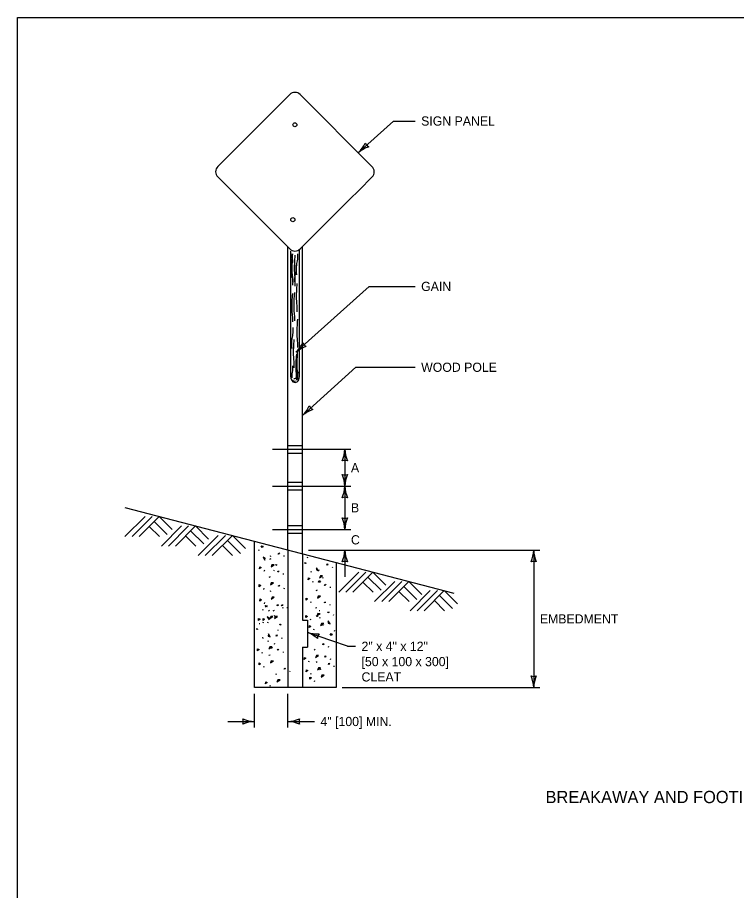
# Model space of a CAD drawing. Extents: x 49991.4 to 50021, y 49987.6 to 50011.4.
# Drawn here: x 49999.38 to 50004.08, y 49993.3 to 49999 of the extents above; entities that cross this region are included whole.
import ezdxf

# ---------------------------------------------------------------- set-up
doc = ezdxf.new("R2010")
doc.units = 0
for name, color, linetype in [('Level 1', 7, 'Continuous'), ('Level 2', 7, 'Continuous'), ('Level 3', 7, 'Continuous'), ('Level 4', 7, 'Continuous'), ('Level 5', 7, 'Continuous')]:
    doc.layers.add(name, color=color, linetype=linetype)

msp = doc.modelspace()

# ---------------------------------------------------------------- linework, layer by layer
at = {"layer": 'Level 1'}
for p, q in [((50001.1615, 49998.4961), (50000.691, 49998.0256)), ((50001.698, 49998.0267), (50001.2287, 49998.4961)), ((50000.691, 49997.9584), (50001.1615, 49997.488)), ((50001.6133, 49997.8726), (50001.6991, 49997.9584)), ((50001.551, 49997.8104), (50001.6133, 49997.8726)), ((50001.2287, 49997.488), (50001.551, 49997.8104)), ((50001.1483, 49995.5227), (50001.1483, 49997.5012)), ((50001.2435, 49995.4979), (50001.2435, 49997.5026)), ((50001.1681, 49996.6528), (50001.1681, 49997.4731)), ((50001.2241, 49996.6528), (50001.2241, 49997.4797)), ((50000.0838, 49995.7996), (50002.2326, 49995.2407)), ((50000.0855, 49995.61), (50000.2167, 49995.7411)), ((50000.1318, 49995.61), (50000.2631, 49995.7411)), ((50000.1773, 49995.61), (50000.3087, 49995.7411)), ((50000.3087, 49995.7411), (50000.3942, 49995.6559)), ((50000.2439, 49995.6761), (50000.3103, 49995.61)), ((50000.2763, 49995.7087), (50000.3616, 49995.6236)), ((50000.3231, 49995.5481), (50000.4542, 49995.6794)), ((50000.3692, 49995.5481), (50000.5004, 49995.6794)), ((50000.4149, 49995.5481), (50000.546, 49995.6794)), ((50000.546, 49995.6794), (50000.6315, 49995.594)), ((50000.4812, 49995.6146), (50000.5478, 49995.5481)), ((50000.5136, 49995.6471), (50000.5991, 49995.5619)), ((50000.5636, 49995.4855), (50000.6947, 49995.6168)), ((50000.6097, 49995.4855), (50000.7409, 49995.6168)), ((50000.6554, 49995.4855), (50000.7865, 49995.6168)), ((50000.7865, 49995.6168), (50000.872, 49995.5314)), ((50000.7217, 49995.552), (50000.7883, 49995.4855)), ((50000.7541, 49995.5845), (50000.8396, 49995.4993)), ((50000.9305, 49994.6238), (50000.9305, 49995.5794)), ((50000.9734, 49995.5491), (50000.987, 49995.5483)), ((50000.9815, 49995.5388), (50000.9734, 49995.5491)), ((50000.987, 49995.5483), (50000.9815, 49995.5388)), ((50000.9631, 49995.5182), (50000.9562, 49995.5208)), ((50001.0858, 49995.4962), (50001.0891, 49995.5039)), ((50001.0931, 49995.498), (50001.0858, 49995.4962)), ((50001.0891, 49995.5039), (50001.0931, 49995.498)), ((50001.1236, 49995.4804), (50001.1243, 49995.4862)), ((50000.9995, 49995.4697), (50000.9866, 49995.4748)), ((50000.9866, 49995.4748), (50000.9991, 49995.455)), ((50000.9991, 49995.455), (50000.9995, 49995.4697)), ((50001.0365, 49995.4638), (50001.0288, 49995.4613)), ((50001.0373, 49995.4771), (50001.0348, 49995.4848)), ((50001.2579, 49995.4372), (50001.2638, 49995.4412)), ((50001.2656, 49995.4339), (50001.2579, 49995.4372)), ((50001.2638, 49995.4412), (50001.2656, 49995.4339)), ((50001.2814, 49995.4717), (50001.2756, 49995.4724)), ((50001.4031, 49995.4235), (50001.4064, 49995.4312)), ((50001.4064, 49995.4312), (50001.4104, 49995.4253)), ((50001.4634, 49995.4409), (50001.4634, 49994.6238)), ((50000.9645, 49995.3999), (50000.9653, 49995.4135)), ((50000.9748, 49995.408), (50000.9645, 49995.3999)), ((50000.9653, 49995.4135), (50000.9748, 49995.408)), ((50000.9954, 49995.3896), (50000.9928, 49995.3827)), ((50001.0439, 49995.426), (50001.0388, 49995.4131)), ((50001.0388, 49995.4131), (50001.0586, 49995.4256)), ((50001.0586, 49995.4256), (50001.0439, 49995.426)), ((50001.0539, 49995.39), (50001.0597, 49995.3893)), ((50001.0697, 49995.4278), (50001.0774, 49995.4245)), ((50001.0715, 49995.4205), (50001.0697, 49995.4278)), ((50001.0774, 49995.4245), (50001.0715, 49995.4205)), ((50001.0825, 49995.3787), (50001.0858, 49995.3864)), ((50001.0898, 49995.3805), (50001.0825, 49995.3787)), ((50001.0858, 49995.3864), (50001.0898, 49995.3805)), ((50001.298, 49995.3846), (50001.3005, 49995.3769)), ((50001.3362, 49995.4067), (50001.3358, 49995.392)), ((50001.3358, 49995.392), (50001.3487, 49995.3869)), ((50001.3487, 49995.3869), (50001.3362, 49995.4067)), ((50001.3538, 49995.3911), (50001.3461, 49995.3886)), ((50001.4104, 49995.4253), (50001.4031, 49995.4235)), ((50001.4409, 49995.4077), (50001.4416, 49995.4135)), ((50001.4807, 49995.247), (50001.6119, 49995.3782)), ((50001.5269, 49995.247), (50001.6583, 49995.3782)), ((50001.5728, 49995.247), (50001.7039, 49995.3782)), ((50001.7039, 49995.3782), (50001.7894, 49995.2932)), ((50001.0332, 49995.3463), (50001.0255, 49995.3438)), ((50001.1203, 49995.3629), (50001.121, 49995.3687)), ((50001.2818, 49995.3272), (50001.2826, 49995.3408)), ((50001.2921, 49995.3353), (50001.2818, 49995.3272)), ((50001.2826, 49995.3408), (50001.2921, 49995.3353)), ((50001.3127, 49995.3169), (50001.3101, 49995.31)), ((50001.3483, 49995.3134), (50001.3538, 49995.3229)), ((50001.3538, 49995.3229), (50001.3619, 49995.3126)), ((50001.3612, 49995.3533), (50001.3561, 49995.3404)), ((50001.3561, 49995.3404), (50001.3759, 49995.3529)), ((50001.3759, 49995.3529), (50001.3612, 49995.3533)), ((50001.3722, 49995.3435), (50001.3791, 49995.3409)), ((50001.6715, 49995.3458), (50001.7568, 49995.2609)), ((50001.7152, 49995.1859), (50001.8463, 49995.3173)), ((50001.7616, 49995.1859), (50001.8927, 49995.3173)), ((50001.807, 49995.1859), (50001.9381, 49995.3173)), ((50001.9381, 49995.3173), (50002.0239, 49995.2318)), ((50000.9612, 49995.2824), (50000.962, 49995.296)), ((50000.9715, 49995.2905), (50000.9612, 49995.2824)), ((50000.962, 49995.296), (50000.9715, 49995.2905)), ((50000.9921, 49995.2721), (50000.9895, 49995.2652)), ((50001.0406, 49995.3085), (50001.0355, 49995.2956)), ((50001.0355, 49995.2956), (50001.0553, 49995.3081)), ((50001.0553, 49995.3081), (50001.0406, 49995.3085)), ((50001.0875, 49995.2853), (50001.0908, 49995.293)), ((50001.0948, 49995.2871), (50001.0875, 49995.2853)), ((50001.0908, 49995.293), (50001.0948, 49995.2871)), ((50001.1253, 49995.2695), (50001.126, 49995.2753)), ((50001.3396, 49995.259), (50001.3319, 49995.2565)), ((50001.3619, 49995.3126), (50001.3483, 49995.3134)), ((50001.3889, 49995.2914), (50001.3922, 49995.2991)), ((50001.3962, 49995.2932), (50001.3889, 49995.2914)), ((50001.3922, 49995.2991), (50001.3962, 49995.2932)), ((50001.4267, 49995.2756), (50001.4274, 49995.2814)), ((50001.6391, 49995.3131), (50001.7052, 49995.247)), ((50001.9057, 49995.2849), (50001.9912, 49995.1995)), ((50000.9662, 49995.189), (50000.967, 49995.2026)), ((50000.967, 49995.2026), (50000.9765, 49995.1971)), ((50001.0382, 49995.2529), (50001.0305, 49995.2504)), ((50001.0456, 49995.2151), (50001.0405, 49995.2022)), ((50001.0405, 49995.2022), (50001.0603, 49995.2147)), ((50001.0603, 49995.2147), (50001.0456, 49995.2151)), ((50001.2676, 49995.1951), (50001.2684, 49995.2087)), ((50001.2779, 49995.2032), (50001.2676, 49995.1951)), ((50001.2684, 49995.2087), (50001.2779, 49995.2032)), ((50001.347, 49995.2212), (50001.3419, 49995.2083)), ((50001.3419, 49995.2083), (50001.3617, 49995.2208)), ((50001.3617, 49995.2208), (50001.347, 49995.2212)), ((50001.8733, 49995.2522), (50001.9398, 49995.1859)), ((50001.947, 49995.1258), (50002.0782, 49995.2569)), ((50001.9932, 49995.1258), (50002.1246, 49995.2569)), ((50002.0388, 49995.1258), (50002.1702, 49995.2569)), ((50002.1378, 49995.2245), (50002.2231, 49995.1394)), ((50002.1702, 49995.2569), (50002.2557, 49995.1717)), ((50000.9765, 49995.1971), (50000.9662, 49995.189)), ((50000.9971, 49995.1787), (50000.9945, 49995.1718)), ((50001.0002, 49995.1596), (50001.0138, 49995.1588)), ((50001.0083, 49995.1493), (50001.0002, 49995.1596)), ((50001.0138, 49995.1588), (50001.0083, 49995.1493)), ((50001.0785, 49995.1587), (50001.0818, 49995.1664)), ((50001.0858, 49995.1605), (50001.0785, 49995.1587)), ((50001.0818, 49995.1664), (50001.0858, 49995.1605)), ((50001.1081, 49995.1587), (50001.1114, 49995.1664)), ((50001.1154, 49995.1605), (50001.1081, 49995.1587)), ((50001.1114, 49995.1664), (50001.1154, 49995.1605)), ((50001.1163, 49995.1429), (50001.117, 49995.1487)), ((50001.1459, 49995.1429), (50001.1466, 49995.1487)), ((50001.2985, 49995.1848), (50001.2959, 49995.1779)), ((50001.3378, 49995.1448), (50001.3301, 49995.1423)), ((50001.3871, 49995.1772), (50001.3904, 49995.1849)), ((50001.3944, 49995.179), (50001.3871, 49995.1772)), ((50001.3904, 49995.1849), (50001.3944, 49995.179)), ((50001.4249, 49995.1614), (50001.4256, 49995.1672)), ((50002.1054, 49995.1919), (50002.1715, 49995.1258)), ((50000.9899, 49995.1287), (50000.983, 49995.1313)), ((50001.0292, 49995.1263), (50001.0215, 49995.1238)), ((50001.0366, 49995.0885), (50001.0315, 49995.0756)), ((50001.0315, 49995.0756), (50001.0513, 49995.0881)), ((50001.0513, 49995.0881), (50001.0366, 49995.0885)), ((50001.0588, 49995.1263), (50001.0511, 49995.1238)), ((50001.0662, 49995.0885), (50001.0611, 49995.0756)), ((50001.0611, 49995.0756), (50001.0809, 49995.0881)), ((50001.0641, 49995.0876), (50001.0616, 49995.0953)), ((50001.0809, 49995.0881), (50001.0662, 49995.0885)), ((50001.2658, 49995.0809), (50001.2666, 49995.0945)), ((50001.2761, 49995.089), (50001.2658, 49995.0809)), ((50001.2666, 49995.0945), (50001.2761, 49995.089)), ((50001.3345, 49995.0904), (50001.3404, 49995.0944)), ((50001.3422, 49995.0871), (50001.3345, 49995.0904)), ((50001.3452, 49995.107), (50001.3401, 49995.0941)), ((50001.3401, 49995.0941), (50001.3599, 49995.1066)), ((50001.3404, 49995.0944), (50001.3422, 49995.0871)), ((50001.3599, 49995.1066), (50001.3452, 49995.107)), ((50001.358, 49995.1249), (50001.3522, 49995.1256)), ((50001.4097, 49995.1121), (50001.413, 49995.1198)), ((50001.417, 49995.1139), (50001.4097, 49995.1121)), ((50001.413, 49995.1198), (50001.417, 49995.1139)), ((50001.4475, 49995.0963), (50001.4482, 49995.1021)), ((50000.9572, 49995.0624), (50000.958, 49995.076)), ((50000.9675, 49995.0705), (50000.9572, 49995.0624)), ((50000.958, 49995.076), (50000.9675, 49995.0705)), ((50000.9666, 49995.0404), (50000.9608, 49995.0411)), ((50000.9881, 49995.0521), (50000.9855, 49995.0452)), ((50000.9868, 49995.0624), (50000.9876, 49995.076)), ((50000.9971, 49995.0705), (50000.9868, 49995.0624)), ((50000.9876, 49995.076), (50000.9971, 49995.0705)), ((50001.0263, 49995.0802), (50001.0134, 49995.0853)), ((50001.0134, 49995.0853), (50001.0259, 49995.0655)), ((50001.0177, 49995.0521), (50001.0151, 49995.0452)), ((50001.0259, 49995.0655), (50001.0263, 49995.0802)), ((50001.0965, 49995.0383), (50001.1042, 49995.035)), ((50001.0983, 49995.031), (50001.0965, 49995.0383)), ((50001.1042, 49995.035), (50001.0983, 49995.031)), ((50001.2884, 49995.0158), (50001.2892, 49995.0294)), ((50001.2892, 49995.0294), (50001.2987, 49995.0239)), ((50001.2967, 49995.0706), (50001.2941, 49995.0637)), ((50001.3604, 49995.0797), (50001.3527, 49995.0772)), ((50001.3678, 49995.0419), (50001.3627, 49995.029)), ((50001.3627, 49995.029), (50001.3825, 49995.0415)), ((50001.3825, 49995.0415), (50001.3678, 49995.0419)), ((50001.3746, 49995.0378), (50001.3771, 49995.0301)), ((50001.4128, 49995.0599), (50001.4124, 49995.0452)), ((50001.4124, 49995.0452), (50001.4253, 49995.0401)), ((50001.4253, 49995.0401), (50001.4128, 49995.0599)), ((50000.9431, 49995.0059), (50000.949, 49995.0099)), ((50000.9508, 49995.0026), (50000.9431, 49995.0059)), ((50000.949, 49995.0099), (50000.9508, 49995.0026)), ((50001.0214, 49994.9754), (50001.021, 49994.9607)), ((50001.0339, 49994.9556), (50001.0214, 49994.9754)), ((50001.0807, 49995.0005), (50001.0865, 49994.9998)), ((50001.2987, 49995.0239), (50001.2884, 49995.0158)), ((50001.3193, 49995.0055), (50001.3167, 49994.9986)), ((50001.4249, 49994.9666), (50001.4304, 49994.9761)), ((50001.4304, 49994.9761), (50001.4385, 49994.9658)), ((50001.4488, 49994.9967), (50001.4557, 49994.9941)), ((50000.9832, 49994.9533), (50000.9857, 49994.9456)), ((50001.0227, 49994.9278), (50001.015, 49994.9253)), ((50001.021, 49994.9607), (50001.0339, 49994.9556)), ((50001.072, 49994.9602), (50001.0753, 49994.9679)), ((50001.0793, 49994.962), (50001.072, 49994.9602)), ((50001.0753, 49994.9679), (50001.0793, 49994.962)), ((50001.1098, 49994.9444), (50001.1105, 49994.9502)), ((50001.4385, 49994.9658), (50001.4249, 49994.9666)), ((50000.9507, 49994.8639), (50000.9515, 49994.8775)), ((50000.961, 49994.872), (50000.9507, 49994.8639)), ((50000.9515, 49994.8775), (50000.961, 49994.872)), ((50001.0301, 49994.89), (50001.025, 49994.8771)), ((50001.025, 49994.8771), (50001.0448, 49994.8896)), ((50001.0448, 49994.8896), (50001.0301, 49994.89)), ((50001.0335, 49994.8821), (50001.039, 49994.8916)), ((50001.0471, 49994.8813), (50001.0335, 49994.8821)), ((50001.039, 49994.8916), (50001.0471, 49994.8813)), ((50001.0574, 49994.9122), (50001.0643, 49994.9096)), ((50001.0819, 49994.868), (50001.0852, 49994.8757)), ((50001.0892, 49994.8698), (50001.0819, 49994.868)), ((50001.0852, 49994.8757), (50001.0892, 49994.8698)), ((50001.3275, 49994.8718), (50001.3198, 49994.8693)), ((50001.3768, 49994.9042), (50001.3801, 49994.9119)), ((50001.3841, 49994.906), (50001.3768, 49994.9042)), ((50001.3801, 49994.9119), (50001.3841, 49994.906)), ((50001.4146, 49994.8884), (50001.4153, 49994.8942)), ((50000.9816, 49994.8536), (50000.979, 49994.8467)), ((50001.0326, 49994.8356), (50001.0249, 49994.8331)), ((50001.1197, 49994.8522), (50001.1204, 49994.858)), ((50001.2555, 49994.8079), (50001.2563, 49994.8215)), ((50001.2658, 49994.816), (50001.2555, 49994.8079)), ((50001.2563, 49994.8215), (50001.2658, 49994.816)), ((50001.3349, 49994.834), (50001.3298, 49994.8211)), ((50001.3298, 49994.8211), (50001.3496, 49994.8336)), ((50001.3496, 49994.8336), (50001.3349, 49994.834)), ((50001.3899, 49994.8235), (50001.3932, 49994.8312)), ((50001.3972, 49994.8253), (50001.3899, 49994.8235)), ((50001.3932, 49994.8312), (50001.3972, 49994.8253)), ((50001.4277, 49994.8077), (50001.4284, 49994.8135)), ((50000.9606, 49994.7717), (50000.9614, 49994.7853)), ((50000.9709, 49994.7798), (50000.9606, 49994.7717)), ((50000.9614, 49994.7853), (50000.9709, 49994.7798)), ((50000.9915, 49994.7614), (50000.9889, 49994.7545)), ((50001.04, 49994.7978), (50001.0349, 49994.7849)), ((50001.0349, 49994.7849), (50001.0547, 49994.7974)), ((50001.0547, 49994.7974), (50001.04, 49994.7978)), ((50001.1247, 49994.7444), (50001.128, 49994.7521)), ((50001.132, 49994.7462), (50001.1247, 49994.7444)), ((50001.128, 49994.7521), (50001.132, 49994.7462)), ((50001.2864, 49994.7976), (50001.2838, 49994.7907)), ((50001.3406, 49994.7911), (50001.3329, 49994.7886)), ((50001.348, 49994.7533), (50001.3429, 49994.7404)), ((50001.3429, 49994.7404), (50001.3627, 49994.7529)), ((50001.3627, 49994.7529), (50001.348, 49994.7533)), ((50001.413, 49994.7757), (50001.4163, 49994.7834)), ((50001.4203, 49994.7775), (50001.413, 49994.7757)), ((50001.4163, 49994.7834), (50001.4203, 49994.7775)), ((50001.4508, 49994.7599), (50001.4515, 49994.7657)), ((50001.0754, 49994.712), (50001.0677, 49994.7095)), ((50001.1625, 49994.7286), (50001.1632, 49994.7344)), ((50001.2686, 49994.7272), (50001.2694, 49994.7408)), ((50001.2789, 49994.7353), (50001.2686, 49994.7272)), ((50001.2694, 49994.7408), (50001.2789, 49994.7353)), ((50001.2917, 49994.6794), (50001.2925, 49994.693)), ((50001.302, 49994.6875), (50001.2917, 49994.6794)), ((50001.2925, 49994.693), (50001.302, 49994.6875)), ((50001.2995, 49994.7169), (50001.2969, 49994.71)), ((50001.3637, 49994.7433), (50001.356, 49994.7408)), ((50001.3711, 49994.7055), (50001.366, 49994.6926)), ((50001.366, 49994.6926), (50001.3858, 49994.7051)), ((50001.3858, 49994.7051), (50001.3711, 49994.7055)), ((50001.0034, 49994.6481), (50001.0042, 49994.6617)), ((50001.0137, 49994.6562), (50001.0034, 49994.6481)), ((50001.0042, 49994.6617), (50001.0137, 49994.6562)), ((50001.0343, 49994.6378), (50001.0317, 49994.6309)), ((50001.0828, 49994.6742), (50001.0777, 49994.6613)), ((50001.0777, 49994.6613), (50001.0975, 49994.6738)), ((50001.0975, 49994.6738), (50001.0828, 49994.6742)), ((50001.3226, 49994.6691), (50001.32, 49994.6622)), ((50001.4634, 49994.6238), (50000.9305, 49994.6238))]:
    msp.add_line(p, q, dxfattribs=at)
msp.add_lwpolyline([(49999.3835, 49998.9992), (50016.7501, 49998.9992), (50016.7501, 49987.7988), (49999.3835, 49987.7988)], close=True, dxfattribs=at)
for centre in [(50001.1945, 49998.2984), (50001.1813, 49997.679)]:
    msp.add_circle(centre, 0.0132, dxfattribs=at)
for centre, radius, start, end in [((50001.1951, 49998.4625), 0.0475, 45.0001, 134.9999), ((50000.7246, 49997.992), 0.0475, 134.9999, 225.0001), ((50001.6644, 49997.992), 0.0483, 315.944, 45.9442), ((50001.1951, 49997.5216), 0.0475, 225.0001, 314.9999)]:
    msp.add_arc(centre, radius, start, end, dxfattribs=at)
msp.add_ellipse((50001.1961, 49996.6528), major_axis=(0, -0.0368), ratio=0.761048, start_param=4.712389, end_param=7.853982, dxfattribs=at)
for points in [[(50001.1714, 49997.4566), (50001.1714, 49997.4435), (50001.1747, 49997.4303), (50001.178, 49997.4006), (50001.1714, 49997.3875), (50001.1747, 49997.3611)], [(50001.178, 49997.4566), (50001.1747, 49997.4039), (50001.1747, 49997.3413), (50001.178, 49997.3051), (50001.178, 49997.2721)], [(50001.1945, 49997.4468), (50001.1912, 49997.3941), (50001.1912, 49997.3315), (50001.1945, 49997.2953), (50001.1945, 49997.2623)], [(50001.211, 49997.4566), (50001.211, 49997.4203), (50001.2044, 49997.3841), (50001.2044, 49997.3182)], [(50001.2011, 49997.3842), (50001.2011, 49997.3479), (50001.1945, 49997.3117), (50001.1945, 49997.2458)], [(50001.1747, 49997.3282), (50001.1714, 49997.315), (50001.1714, 49997.3084), (50001.178, 49997.2985), (50001.1813, 49997.2788), (50001.178, 49997.2524)], [(50001.2077, 49997.2623), (50001.2044, 49997.2096), (50001.2044, 49997.147), (50001.2077, 49997.1108), (50001.2077, 49997.0778)], [(50001.178, 49997.1964), (50001.1747, 49997.1437), (50001.1747, 49997.0811), (50001.178, 49997.0449), (50001.178, 49997.0119)], [(50001.1912, 49997.203), (50001.1879, 49997.1503), (50001.1879, 49997.0877), (50001.1912, 49997.0515), (50001.1912, 49997.0185)], [(50001.211, 49997.0284), (50001.2077, 49996.9757), (50001.2077, 49996.9131), (50001.211, 49996.8769), (50001.211, 49996.8439)], [(50001.1813, 49996.9757), (50001.1813, 49996.9394), (50001.1747, 49996.9032), (50001.1747, 49996.8373)], [(50001.1879, 49996.8966), (50001.1846, 49996.8439), (50001.1846, 49996.7813), (50001.1879, 49996.7451), (50001.1879, 49996.7121)], [(50001.2044, 49996.8011), (50001.2011, 49996.7484), (50001.2011, 49996.6858), (50001.2044, 49996.6496), (50001.2048, 49996.6304)], [(50001.211, 49996.8208), (50001.2077, 49996.7681), (50001.2077, 49996.7055), (50001.211, 49996.6693), (50001.211, 49996.6363)], [(50001.178, 49996.7253), (50001.178, 49996.6924), (50001.1747, 49996.6726), (50001.1747, 49996.6462)], [(50001.2142, 49996.6858), (50001.2077, 49996.6594), (50001.2011, 49996.6462), (50001.1945, 49996.6396), (50001.1879, 49996.6396)], [(50001.178, 49996.6331), (50001.1846, 49996.6265), (50001.1978, 49996.6265)]]:
    msp.add_spline(points, degree=3, dxfattribs=at)
at = {"layer": 'Level 3'}
for p, q in [((50001.8386, 49998.3231), (50001.6087, 49998.116)), ((50001.8386, 49998.3231), (50001.9788, 49998.3231)), ((50001.6791, 49997.2433), (50001.2014, 49996.813)), ((50001.6791, 49997.2433), (50001.9788, 49997.2433)), ((50001.5935, 49996.7155), (50001.2435, 49996.4002)), ((50001.5935, 49996.7155), (50001.9788, 49996.7155)), ((50001.5206, 49996.1801), (50001.5206, 49995.9396)), ((50001.5206, 49995.9396), (50001.5206, 49995.6563)), ((50001.2835, 49995.5213), (50002.7938, 49995.5213)), ((50001.5206, 49995.5213), (50001.5206, 49995.3478)), ((50002.7538, 49995.5213), (50002.7538, 49994.6238)), ((50001.4363, 49994.929), (50001.2759, 49994.9847)), ((50001.537, 49994.8938), (50001.4363, 49994.929)), ((50001.537, 49994.8938), (50001.5897, 49994.8938)), ((50000.9305, 49994.3628), (50000.9305, 49994.5838)), ((50001.1483, 49994.3628), (50001.1483, 49994.5838)), ((50001.5034, 49994.6238), (50002.7938, 49994.6238)), ((50000.7571, 49994.4028), (50000.9305, 49994.4028)), ((50001.1483, 49994.4028), (50001.3217, 49994.4028))]:
    msp.add_line(p, q, dxfattribs=at)
for centre, radius, start, end in [((50001.4444, 49998.2812), 0.233, 314.8407, 334.0905), ((50001.704, 49998.2018), 0.0548, 204.1522, 239.8745), ((50001.7506, 49997.9448), 0.2223, 109.4694, 129.6529), ((50001.0371, 49996.9782), 0.233, 314.8403, 334.0902), ((50001.2967, 49996.8988), 0.0548, 204.1519, 239.8742), ((50001.3433, 49996.6418), 0.2223, 109.469, 129.6526), ((50001.0792, 49996.5654), 0.233, 314.8416, 334.0915), ((50001.3388, 49996.486), 0.0548, 204.1532, 239.8755), ((50001.3854, 49996.229), 0.2223, 109.4703, 129.6539), ((50001.2985, 49996.1893), 0.2223, 337.456, 357.6395), ((50001.7533, 49996.1916), 0.233, 182.8273, 202.0772), ((50001.5206, 49996.0519), 0.0548, 72.1388, 107.8612), ((50001.5206, 49996.0678), 0.0548, 252.1388, 287.8612), ((50001.2879, 49995.9281), 0.233, 2.8273, 22.0772), ((50001.7427, 49995.9304), 0.2223, 157.456, 177.6395), ((50001.2985, 49995.9488), 0.2223, 337.456, 357.6395), ((50001.7533, 49995.9511), 0.233, 182.8273, 202.0772), ((50001.5206, 49995.8114), 0.0548, 72.1388, 107.8612), ((50001.5206, 49995.7845), 0.0548, 252.1388, 287.8612), ((50001.2879, 49995.6448), 0.233, 2.8273, 22.0772), ((50001.7427, 49995.6471), 0.2223, 157.456, 177.6395), ((50001.2984, 49995.5305), 0.2224, 337.456, 357.6395), ((50001.7534, 49995.5328), 0.2331, 182.8273, 202.0772), ((50002.5317, 49995.5305), 0.2223, 337.456, 357.6395), ((50002.9865, 49995.5328), 0.233, 182.8273, 202.0772), ((50001.5206, 49995.393), 0.0548, 72.1388, 107.8612), ((50002.7538, 49995.3931), 0.0548, 72.1388, 107.8612), ((50001.1943, 49994.7779), 0.2223, 48.2759, 68.4594), ((50001.3415, 49995.2083), 0.233, 253.6472, 272.8971), ((50001.397, 49994.9426), 0.0548, 142.9587, 178.6811), ((50002.7538, 49994.752), 0.0548, 252.1388, 287.8612), ((50002.5211, 49994.6123), 0.233, 2.8273, 22.0772), ((50002.9759, 49994.6146), 0.2223, 157.456, 177.6395), ((50000.9397, 49994.6249), 0.2223, 247.456, 267.6395), ((50000.8023, 49994.4028), 0.0548, 342.1388, 17.8612), ((50000.942, 49994.1701), 0.233, 92.8273, 112.0772), ((50001.1368, 49994.6355), 0.233, 272.8273, 292.0772), ((50001.1391, 49994.1807), 0.2223, 67.456, 87.6395), ((50001.2765, 49994.4028), 0.0548, 162.1388, 197.8612)]:
    msp.add_arc(centre, radius, start, end, dxfattribs=at)
at = {"layer": 'Level 4'}
for p, q in [((50001.1483, 49996.2051), (50001.2435, 49996.2051)), ((50001.1483, 49996.1551), (50001.2435, 49996.1551)), ((50001.1483, 49995.9646), (50001.2435, 49995.9646)), ((50001.1483, 49995.9146), (50001.2435, 49995.9146)), ((50001.1483, 49995.6813), (50001.2435, 49995.6813)), ((50001.1483, 49995.6313), (50001.2435, 49995.6313)), ((50001.1483, 49995.5227), (50001.1483, 49994.6257)), ((50001.2435, 49995.4979), (50001.2435, 49995.0635)), ((50001.2435, 49995.0635), (50001.2759, 49995.0635)), ((50001.2759, 49995.0635), (50001.2759, 49994.8889)), ((50001.2435, 49994.8889), (50001.2435, 49994.624)), ((50001.2435, 49994.8889), (50001.2759, 49994.8889))]:
    msp.add_line(p, q, dxfattribs=at)
at = {"layer": 'Level 5'}
for p, q in [((50001.0483, 49996.1801), (50001.5606, 49996.1801)), ((50001.0483, 49995.9396), (50001.5606, 49995.9396)), ((50001.0483, 49995.6563), (50001.5606, 49995.6563))]:
    msp.add_line(p, q, dxfattribs=at)

# ---------------------------------------------------------------- texts
at = {"layer": 'Level 2'}
for s, height, p in [('SIGN PANEL', 0.06, (50002.0188, 49998.2931)), ('GAIN', 0.06, (50002.0188, 49997.2133)), ('WOOD POLE', 0.06, (50002.0188, 49996.6855)), ('A', 0.06, (50001.5606, 49996.0298)), ('B', 0.06, (50001.5606, 49995.768)), ('C', 0.06, (50001.5606, 49995.5588)), ('EMBEDMENT', 0.06, (50002.7938, 49995.0426)), ('2" x 4" x 12"', 0.06, (50001.6297, 49994.8638)), ('[50 x 100 x 300]', 0.06, (50001.6297, 49994.7638)), ('CLEAT', 0.06, (50001.6297, 49994.6638)), ('4" [100] MIN.', 0.06, (50001.3617, 49994.3728)), ('BREAKAWAY AND FOOTING DETAILS', 0.08, (50002.831, 49993.8697))]:
    msp.add_text(s, height=height, dxfattribs=at).set_placement(p)

doc.saveas('drawing.dxf')
